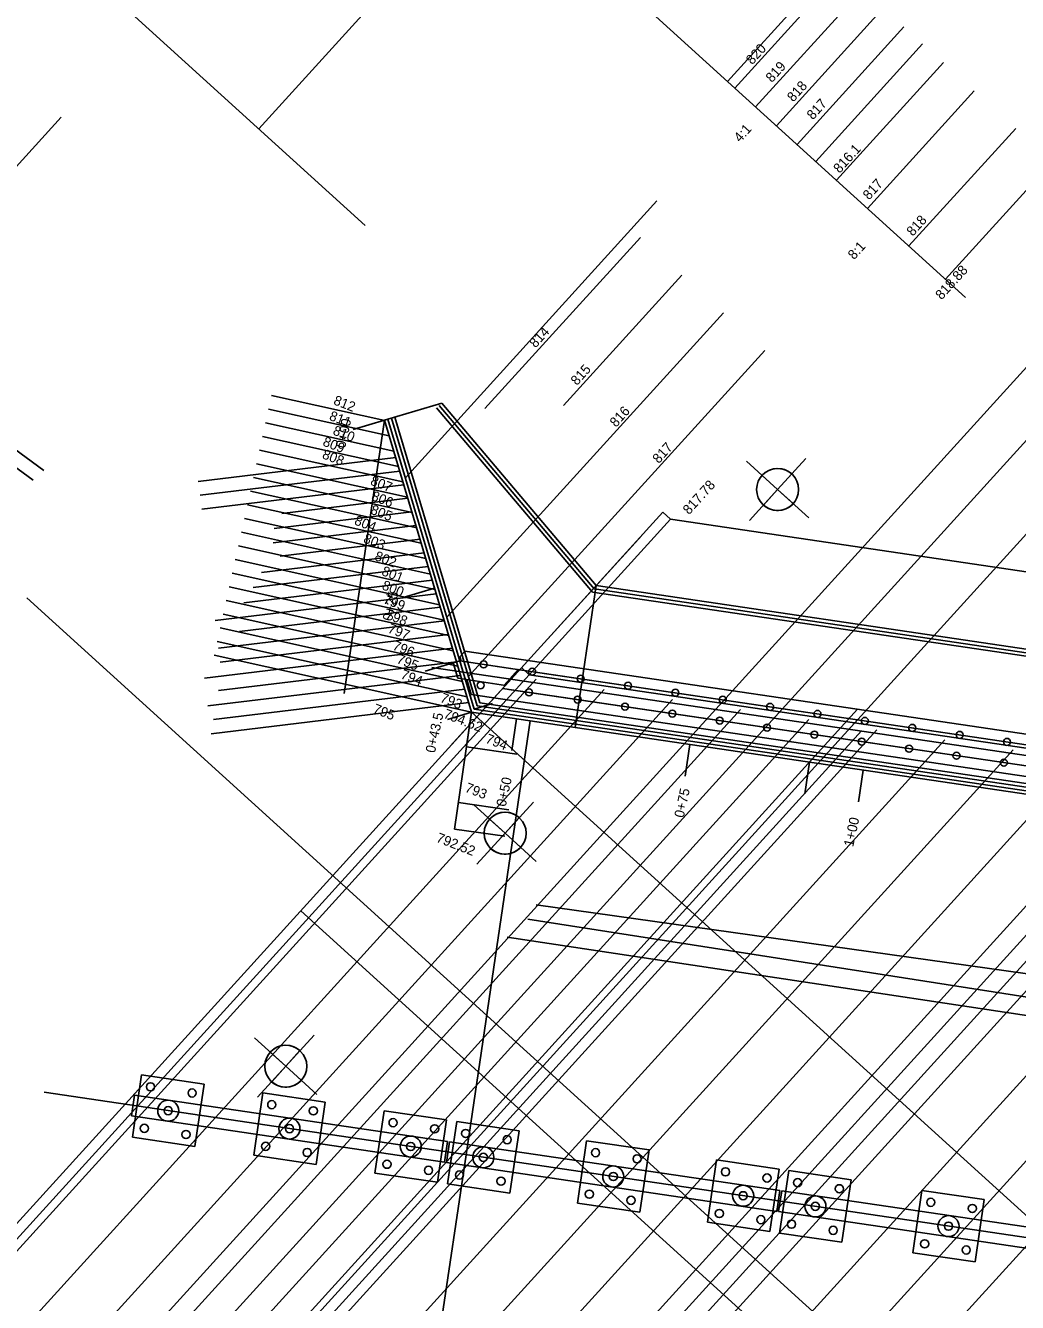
# Model space of a CAD drawing. Extents: x 1465887 to 1476191, y 569684 to 581027.
# Drawn here: x 1469836.1 to 1469977.6, y 574066.2 to 574248.6 of the extents above; entities that cross this region are included whole.
import ezdxf

# ---------------------------------------------------------------- set-up
doc = ezdxf.new("R2010")
doc.units = 0
for name, color, linetype in [('BR_P_Beam_Centerline', 7, 'Continuous'), ('BR_P_Brg_Centerline', 7, 'Continuous'), ('BR_P_Gen_Approach_Slab', 7, 'Continuous'), ('BR_P_Gen_Ground_Slope', 7, 'Continuous'), ('BR_P_Gen_Perforated_Pipe', 7, 'Continuous'), ('BR_P_Gen_Phase_Construction', 7, 'Continuous'), ('BR_P_Gen_Porous_Backfill', 7, 'Continuous'), ('BR_P_Gen_Profile_Grade', 7, 'Continuous'), ('BR_P_Gen_Slope_Protection', 7, 'Continuous'), ('BR_P_Rail_Object', 7, 'Continuous'), ('BR_P_Sub_Centerline', 7, 'Continuous'), ('BR_P_Sub_Deep_Centerline', 7, 'Continuous'), ('BR_P_Sub_Deep_Hidden', 7, 'Continuous'), ('BR_P_Sub_Foot_Hidden', 7, 'Continuous'), ('BR_P_Sub_Hidden', 7, 'Continuous'), ('BR_P_Sub_Object', 7, 'Continuous'), ('GT_Project_Soil_Boring', 7, 'Continuous'), ('PV_X_EOP', 7, 'Continuous'), ('PV_X_Shoulder', 7, 'Continuous'), ('SC_Scratch1', 7, 'Continuous'), ('SC_Scratch2', 7, 'Continuous'), ('UT_X_Water', 7, 'Continuous')]:
    doc.layers.add(name, color=color, linetype=linetype)

msp = doc.modelspace()

# ---------------------------------------------------------------- linework, layer by layer
at = {"layer": 'BR_P_Beam_Centerline'}
for p, q in [((1469797.88, 574032.91), (1469908.95, 574155.21)), ((1469807.6, 574031.47), (1469918.67, 574153.77)), ((1469817.33, 574030.03), (1469928.4, 574152.33)), ((1469827.05, 574028.59), (1469938.12, 574150.89)), ((1469836.78, 574027.15), (1469947.84, 574149.45)), ((1469846.5, 574025.71), (1469957.57, 574148.01)), ((1469856.23, 574024.27), (1469967.29, 574146.57)), ((1469865.95, 574022.83), (1469977.02, 574145.13)), ((1469875.67, 574021.39), (1469986.74, 574143.69)), ((1469885.4, 574019.95), (1469996.47, 574142.25)), ((1469895.12, 574018.51), (1470006.19, 574140.81)), ((1469904.85, 574017.07), (1470015.91, 574139.37)), ((1469914.57, 574015.63), (1470025.64, 574137.93)), ((1469924.3, 574014.19), (1470035.36, 574136.49))]:
    msp.add_line(p, q, dxfattribs=at)
at = {"layer": 'BR_P_Brg_Centerline'}
msp.add_line((1469894.04, 574156.91), (1470052.69, 574133.42), dxfattribs=at)
at = {"layer": 'BR_P_Gen_Approach_Slab'}
for p, q in [((1469928.13, 574178.07), (1470067.44, 574157.44)), ((1469907.96, 574155.86), (1470047.28, 574135.23))]:
    msp.add_line(p, q, dxfattribs=at)
at = {"layer": 'BR_P_Gen_Ground_Slope'}
for p, q in [((1469884.52, 574220.03), (1469752.3, 574340.1)), ((1469937.3, 574239.64), (1469952.56, 574256.43)), ((1469940.27, 574236.95), (1469955.52, 574253.75)), ((1469943.23, 574234.26), (1469958.48, 574251.06)), ((1469946.19, 574231.57), (1469961.44, 574248.37)), ((1469956.23, 574222.45), (1469971.48, 574239.25)), ((1469819.44, 574211.59), (1469841.12, 574235.46)), ((1469962.15, 574217.08), (1469977.4, 574233.87)), ((1469967.36, 574212.34), (1469982.61, 574229.14)), ((1469901.63, 574193.87), (1469923.82, 574218.31)), ((1469912.84, 574194.31), (1469929.75, 574212.93)), ((1469896.2, 574164.09), (1469935.67, 574207.55)), ((1469899.26, 574155.56), (1469941.59, 574202.17)), ((1469821.79, 574197.35), (1469838.65, 574185.03)), ((1469819.59, 574196.48), (1469837.16, 574183.64)), ((1469887.32, 574192.17), (1469871.18, 574195.74)), ((1469887.97, 574189.98), (1469870.75, 574193.79)), ((1469888.63, 574187.79), (1469870.32, 574191.84)), ((1469889.28, 574185.59), (1469869.88, 574189.89)), ((1469888.9, 574186.88), (1469860.72, 574183.47)), ((1469889.93, 574183.4), (1469869.45, 574187.93)), ((1469889.47, 574184.93), (1469860.96, 574181.48)), ((1469890.58, 574181.21), (1469869.02, 574185.98)), ((1469890.05, 574182.99), (1469861.2, 574179.5)), ((1469891.24, 574179.01), (1469868.59, 574184.03)), ((1469891.89, 574176.82), (1469868.16, 574182.08)), ((1469890.63, 574181.05), (1469872.65, 574178.87)), ((1469892.54, 574174.63), (1469867.72, 574180.12)), ((1469891.21, 574179.1), (1469871.56, 574176.72)), ((1469893.2, 574172.44), (1469867.29, 574178.17)), ((1469891.79, 574177.16), (1469871.38, 574174.69)), ((1469893.85, 574170.24), (1469866.86, 574176.22)), ((1469894.5, 574168.05), (1469866.43, 574174.26)), ((1469892.37, 574175.21), (1469872.38, 574172.79)), ((1469895.15, 574165.86), (1469865.99, 574172.31)), ((1469892.95, 574173.27), (1469869.73, 574170.46)), ((1469895.81, 574163.66), (1469865.56, 574170.36)), ((1469893.53, 574171.32), (1469868.57, 574168.3)), ((1469896.46, 574161.47), (1469865.13, 574168.41)), ((1469894.11, 574169.38), (1469867.22, 574166.13)), ((1469894.68, 574167.43), (1469863.12, 574163.62)), ((1469897.11, 574159.28), (1469864.7, 574166.45)), ((1469897.77, 574157.09), (1469864.26, 574164.5)), ((1469895.26, 574165.49), (1469866.61, 574162.02)), ((1469895.84, 574163.54), (1469863.6, 574159.64)), ((1469898.42, 574154.89), (1469863.83, 574162.55)), ((1469896.42, 574161.6), (1469863.84, 574157.66)), ((1469897, 574159.66), (1469861.59, 574155.37)), ((1469899.07, 574152.7), (1469863.4, 574160.6)), ((1469899.72, 574150.51), (1469862.97, 574158.64)), ((1469897.58, 574157.71), (1469863.6, 574153.6)), ((1469898.16, 574155.77), (1469862.07, 574151.4)), ((1469898.74, 574153.82), (1469862.88, 574149.48)), ((1469899.32, 574151.88), (1469862.55, 574147.43)), ((1469899.72, 574150.51), (1469897.3, 574133.83)), ((1469899, 574145.55), (1469906.18, 574144.51)), ((1469897.86, 574137.63), (1469905.03, 574136.59)), ((1469897.3, 574133.83), (1469904.48, 574132.79))]:
    msp.add_line(p, q, dxfattribs=at)
at = {"layer": 'BR_P_Gen_Perforated_Pipe'}
for p, q in [((1469894.7, 574193.98), (1469916.98, 574167.66)), ((1469895.08, 574194.3), (1469917.24, 574168.13)), ((1469888.27, 574192.48), (1469900.5, 574151.4)), ((1469888.75, 574192.63), (1469900.89, 574151.85)), ((1469917.24, 574168.13), (1470044.7, 574149.26)), ((1469916.98, 574167.66), (1470044.86, 574148.73)), ((1469900.89, 574151.85), (1470043.82, 574130.69)), ((1469899.72, 574150.51), (1469997.64, 574061.59)), ((1469900.5, 574151.4), (1470044.02, 574130.16))]:
    msp.add_line(p, q, dxfattribs=at)
at = {"layer": 'BR_P_Gen_Phase_Construction'}
for p, q in [((1469839.72, 574024.19), (1469954.83, 574150.94)), ((1469845.12, 574026.42), (1469955.38, 574147.83)), ((1469886.75, 574017.22), (1470001.86, 574143.98)), ((1469892.16, 574019.46), (1469999.98, 574138.19))]:
    msp.add_line(p, q, dxfattribs=at)
at = {"layer": 'BR_P_Gen_Porous_Backfill'}
for p, q in [((1469887.79, 574192.34), (1469895.46, 574194.62)), ((1469895.46, 574194.62), (1469917.5, 574168.6)), ((1469917.5, 574168.6), (1470044.55, 574149.79))]:
    msp.add_line(p, q, dxfattribs=at)
at = {"layer": 'BR_P_Gen_Profile_Grade'}
msp.add_line((1465892.5, 569689.56), (1476184.47, 581022.69), dxfattribs=at)
at = {"layer": 'BR_P_Gen_Slope_Protection'}
for p, q in [((1469887.31, 574192.2), (1469887.79, 574192.34)), ((1469887.31, 574192.2), (1469899.72, 574150.51)), ((1469887.79, 574192.34), (1469900.11, 574150.95)), ((1469899.72, 574150.51), (1470043.8, 574129.18)), ((1469900.11, 574150.95), (1470044.4, 574129.59))]:
    msp.add_line(p, q, dxfattribs=at)
at = {"layer": 'BR_P_Rail_Object'}
for p, q in [((1469774.81, 574011.47), (1469927.02, 574179.08)), ((1469928.13, 574178.07), (1469927.02, 574179.08)), ((1469775.92, 574010.46), (1469928.13, 574178.07)), ((1469907.96, 574155.86), (1469906.85, 574156.87))]:
    msp.add_line(p, q, dxfattribs=at)
at = {"layer": 'BR_P_Sub_Centerline'}
msp.add_line((1469838.73, 574096.23), (1469997.31, 574072.75), dxfattribs=at)
at = {"layer": 'BR_P_Sub_Deep_Centerline'}
for p, q in [((1469903.37, 574157.04), (1470048.77, 574135.52)), ((1470044.7, 574133.09), (1469905.02, 574153.77))]:
    msp.add_line(p, q, dxfattribs=at)
at = {"layer": 'BR_P_Sub_Deep_Hidden'}
for centre, radius in [((1469901.45, 574157.33), 0.5), ((1469908.37, 574156.3), 0.5), ((1469915.3, 574155.28), 0.5), ((1469901.01, 574154.36), 0.5), ((1469907.93, 574153.34), 0.5), ((1469922.06, 574154.28), 0.5), ((1469928.82, 574153.28), 0.5), ((1469914.86, 574152.31), 0.5), ((1469921.62, 574151.31), 0.5), ((1469935.58, 574152.28), 0.5), ((1469942.34, 574151.27), 0.5), ((1469928.38, 574150.31), 0.5), ((1469935.14, 574149.31), 0.5), ((1469949.1, 574150.27), 0.5), ((1469955.86, 574149.27), 0.5), ((1469941.9, 574148.31), 0.5), ((1469962.62, 574148.27), 0.5), ((1469948.66, 574147.31), 0.5), ((1469955.42, 574146.31), 0.5), ((1469969.38, 574147.27), 0.5), ((1469976.14, 574146.27), 0.5), ((1469962.18, 574145.3), 0.5), ((1469968.94, 574144.3), 0.5), ((1469975.7, 574143.3), 0.5), ((1469853.89, 574097.02), 0.583), ((1469859.83, 574096.14), 0.583), ((1469856.42, 574093.61), 0.583), ((1469871.2, 574094.46), 0.583), ((1469877.14, 574093.58), 0.583), ((1469853.01, 574091.08), 0.583), ((1469873.73, 574091.05), 0.583), ((1469888.52, 574091.89), 0.583), ((1469894.45, 574091.01), 0.583), ((1469858.95, 574090.21), 0.583), ((1469898.87, 574090.36), 0.583), ((1469904.81, 574089.48), 0.583), ((1469870.33, 574088.52), 0.583), ((1469876.26, 574087.64), 0.583), ((1469891.04, 574088.49), 0.583), ((1469917.42, 574087.61), 0.583), ((1469887.64, 574085.96), 0.583), ((1469901.4, 574086.95), 0.583), ((1469923.35, 574086.74), 0.583), ((1469893.57, 574085.08), 0.583), ((1469897.99, 574084.43), 0.583), ((1469903.93, 574083.55), 0.583), ((1469919.95, 574084.21), 0.583), ((1469935.97, 574084.87), 0.583), ((1469941.9, 574083.99), 0.583), ((1469946.27, 574083.34), 0.583), ((1469952.21, 574082.46), 0.583), ((1469916.54, 574081.68), 0.583), ((1469922.48, 574080.8), 0.583), ((1469938.49, 574081.46), 0.583), ((1469948.8, 574079.94), 0.583), ((1469965.27, 574080.53), 0.583), ((1469935.09, 574078.93), 0.583), ((1469941.02, 574078.05), 0.583), ((1469971.21, 574079.65), 0.583), ((1469945.39, 574077.41), 0.583), ((1469951.33, 574076.53), 0.583), ((1469967.8, 574077.12), 0.583), ((1469964.39, 574074.59), 0.583), ((1469970.33, 574073.72), 0.583)]:
    msp.add_circle(centre, radius, dxfattribs=at)
at = {"layer": 'BR_P_Sub_Foot_Hidden'}
for p, q in [((1469898.06, 574158.43), (1469898.76, 574159.24)), ((1469898.76, 574159.24), (1470049.69, 574136.9)), ((1469898.06, 574158.43), (1469898.25, 574157.8)), ((1469899.03, 574155.16), (1469899.66, 574153.04)), ((1469899.66, 574153.04), (1470045.83, 574131.4)), ((1469851.31, 574089.82), (1469852.63, 574098.72)), ((1469852.63, 574098.72), (1469861.53, 574097.4)), ((1469861.53, 574097.4), (1469860.21, 574088.5)), ((1469868.62, 574087.26), (1469869.94, 574096.16)), ((1469869.94, 574096.16), (1469878.84, 574094.84)), ((1469878.84, 574094.84), (1469877.52, 574085.94)), ((1469885.93, 574084.69), (1469887.25, 574093.6)), ((1469887.25, 574093.6), (1469896.15, 574092.28)), ((1469896.15, 574092.28), (1469894.84, 574083.38)), ((1469896.29, 574083.16), (1469897.61, 574092.06)), ((1469897.61, 574092.06), (1469906.51, 574090.75)), ((1469851.31, 574089.82), (1469860.21, 574088.5)), ((1469906.51, 574090.75), (1469905.19, 574081.84)), ((1469914.84, 574080.42), (1469916.15, 574089.32)), ((1469916.15, 574089.32), (1469925.06, 574088)), ((1469925.06, 574088), (1469923.74, 574079.1)), ((1469868.62, 574087.26), (1469877.52, 574085.94)), ((1469933.38, 574077.67), (1469934.7, 574086.57)), ((1469934.7, 574086.57), (1469943.61, 574085.25)), ((1469885.93, 574084.69), (1469894.84, 574083.38)), ((1469943.61, 574085.25), (1469942.29, 574076.35)), ((1469943.69, 574076.14), (1469945.01, 574085.05)), ((1469945.01, 574085.05), (1469953.91, 574083.73)), ((1469896.29, 574083.16), (1469905.19, 574081.84)), ((1469953.91, 574083.73), (1469952.59, 574074.83)), ((1469962.69, 574073.33), (1469964.01, 574082.23)), ((1469964.01, 574082.23), (1469972.91, 574080.92)), ((1469972.91, 574080.92), (1469971.59, 574072.01)), ((1469914.84, 574080.42), (1469923.74, 574079.1)), ((1469933.38, 574077.67), (1469942.29, 574076.35)), ((1469943.69, 574076.14), (1469952.59, 574074.83)), ((1469962.69, 574073.33), (1469971.59, 574072.01))]:
    msp.add_line(p, q, dxfattribs=at)
at = {"layer": 'BR_P_Sub_Hidden'}
for p, q in [((1469904.15, 574153.9), (1469906.58, 574156.57)), ((1469904.36, 574154.37), (1469906.38, 574156.6)), ((1469906.58, 574156.57), (1470049.47, 574135.41)), ((1469904.15, 574153.9), (1470047.04, 574132.74)), ((1469851.61, 574095.84), (1469851.17, 574092.87)), ((1469851.61, 574095.84), (1469896.29, 574089.23)), ((1469895.85, 574086.26), (1469851.17, 574092.87)), ((1469895.85, 574086.26), (1469896.29, 574089.23)), ((1469896.59, 574089.18), (1469896.15, 574086.21)), ((1469896.59, 574089.18), (1469943.74, 574082.2)), ((1469943.3, 574079.23), (1469896.15, 574086.21)), ((1469943.3, 574079.23), (1469943.74, 574082.2)), ((1469943.99, 574082.16), (1469943.55, 574079.2)), ((1469943.99, 574082.16), (1469992.05, 574075.05)), ((1469991.61, 574072.08), (1469943.55, 574079.2))]:
    msp.add_line(p, q, dxfattribs=at)
msp.add_lwpolyline([(1469904.36, 574154.37), (1469904.56, 574154.34), (1469906.58, 574156.57), (1469906.38, 574156.6)], close=True, dxfattribs=at)
for centre in [(1469856.42, 574093.61), (1469873.73, 574091.05), (1469891.04, 574088.49), (1469901.4, 574086.95), (1469919.95, 574084.21), (1469938.49, 574081.46), (1469948.8, 574079.94), (1469967.8, 574077.12)]:
    msp.add_circle(centre, 1.5, dxfattribs=at)
at = {"layer": 'BR_P_Sub_Object'}
for p, q in [((1469898.07, 574157.83), (1469897.11, 574157.54)), ((1469897.11, 574157.54), (1469897.76, 574155.35)), ((1469898.07, 574157.83), (1469906.58, 574156.57)), ((1469897.76, 574155.35), (1469904.56, 574154.34))]:
    msp.add_line(p, q, dxfattribs=at)
at = {"layer": 'GT_Project_Soil_Boring'}
for p, q in [((1469943.41, 574182.31), (1469938.97, 574186.34)), ((1469943.41, 574182.31), (1469947.45, 574186.75)), ((1469945.43, 574184.53), (1469943.41, 574182.31)), ((1469943.41, 574182.31), (1469941.19, 574184.33)), ((1469943.41, 574182.31), (1469939.38, 574177.87)), ((1469941.4, 574180.09), (1469943.41, 574182.31)), ((1469943.41, 574182.31), (1469947.85, 574178.28)), ((1469943.41, 574182.31), (1469945.63, 574180.29)), ((1469904.51, 574133.23), (1469900.06, 574137.27)), ((1469904.51, 574133.23), (1469908.54, 574137.68)), ((1469904.51, 574133.23), (1469902.29, 574135.25)), ((1469906.52, 574135.45), (1469904.51, 574133.23)), ((1469904.51, 574133.23), (1469900.47, 574128.79)), ((1469902.49, 574131.01), (1469904.51, 574133.23)), ((1469904.51, 574133.23), (1469908.95, 574129.2)), ((1469904.51, 574133.23), (1469906.73, 574131.22)), ((1469873.2, 574099.96), (1469877.24, 574104.4)), ((1469873.2, 574099.96), (1469868.76, 574104)), ((1469873.2, 574099.96), (1469870.98, 574101.98)), ((1469875.22, 574102.18), (1469873.2, 574099.96)), ((1469873.2, 574099.96), (1469869.17, 574095.52)), ((1469871.19, 574097.74), (1469873.2, 574099.96)), ((1469873.2, 574099.96), (1469877.64, 574095.93)), ((1469873.2, 574099.96), (1469875.42, 574097.95))]:
    msp.add_line(p, q, dxfattribs=at)
for centre in [(1469943.41, 574182.31), (1469904.51, 574133.23), (1469873.2, 574099.96)]:
    msp.add_circle(centre, 3, dxfattribs=at)
for centre, start, end in [((1469943.41, 574182.31), 47.7565, 137.7565), ((1469943.41, 574182.31), 227.7565, 317.7565), ((1469904.51, 574133.23), 47.7565, 137.7565), ((1469904.51, 574133.23), 227.7565, 317.7565), ((1469873.2, 574099.96), 47.7565, 137.7565), ((1469873.2, 574099.96), 227.7565, 317.7565)]:
    msp.add_arc(centre, 3, start, end, dxfattribs=at)
at = {"layer": 'PV_X_EOP'}
msp.add_line((1469904.79, 574118.39), (1470006.8, 574102.99), dxfattribs=at)
at = {"layer": 'PV_X_Shoulder'}
msp.add_line((1469908.94, 574123), (1470011.71, 574108.53), dxfattribs=at)
at = {"layer": 'SC_Scratch1'}
for p, q in [((1465887.32, 569694.27), (1476179.29, 581027.4)), ((1465899.17, 569683.51), (1476191.13, 581016.64)), ((1469869.34, 574233.82), (1472383.88, 577002.73)), ((1469936.27, 574240.58), (1469951.52, 574257.38)), ((1469918.13, 574257.05), (1469970.23, 574209.74)), ((1469948.85, 574229.15), (1469964.11, 574245.95)), ((1469951.81, 574226.46), (1469967.07, 574243.26)), ((1469890.28, 574183.99), (1469926.18, 574223.52)), ((1469881.54, 574153.2), (1469887.31, 574192.2)), ((1469882.83, 574190.86), (1469887.31, 574192.2)), ((1469896.66, 574145.65), (1469924.01, 574175.76)), ((1469889.96, 574166.9), (1469894.45, 574168.24)), ((1469917.5, 574168.6), (1469914.5, 574148.32)), ((1469893.11, 574156.35), (1469897.59, 574157.69)), ((1469900.11, 574150.95), (1469902.7, 574151.73)), ((1469896.28, 574149.48), (1469899.72, 574150.51)), ((1469899.05, 574145.98), (1469899.72, 574150.51)), ((1469898.93, 574087.32), (1469908.1, 574149.27)), ((1469905.48, 574145.03), (1469906.15, 574149.56)), ((1469930.21, 574141.36), (1469930.88, 574145.89)), ((1469947.28, 574138.84), (1469947.95, 574143.37)), ((1469954.94, 574137.7), (1469955.61, 574142.23)), ((1469889.68, 574024.88), (1469898.93, 574087.32))]:
    msp.add_line(p, q, dxfattribs=at)
at = {"layer": 'SC_Scratch2'}
for p, q in [((1469967.62, 574047.52), (1469836.22, 574166.85)), ((1469964.17, 574041.49), (1469875.33, 574122.16))]:
    msp.add_line(p, q, dxfattribs=at)
at = {"layer": 'UT_X_Water'}
msp.add_line((1469907.74, 574120.94), (1470009.3, 574105.12), dxfattribs=at)

# ---------------------------------------------------------------- texts
at = {"layer": 'BR_P_Gen_Ground_Slope'}
for s, rotation, p in [('820', 47.7564, (1469939.78, 574242.88)), ('819', 47.7564, (1469942.59, 574240.33)), ('818', 47.7564, (1469945.64, 574237.56)), ('817', 47.7564, (1469948.45, 574235.01)), ('4:1', 47.7564, (1469938.05, 574231.79)), ('816.1', 47.7564, (1469952.25, 574227.38)), ('817', 47.7564, (1469956.45, 574223.57)), ('818', 47.7564, (1469962.7, 574218.39)), ('8:1', 47.7564, (1469954.32, 574215.03)), ('818.88', 47.7564, (1469966.81, 574209.31)), ('814', 47.7564, (1469908.85, 574202.44)), ('815', 47.7564, (1469914.76, 574197.08)), ('812', 338.5632, (1469879.9, 574194.51)), ('816', 47.7564, (1469920.33, 574191.11)), ('811', 338.5632, (1469879.29, 574192.29)), ('810', 338.5632, (1469879.81, 574190.2)), ('809', 338.5632, (1469878.37, 574188.62)), ('817', 47.7564, (1469926.44, 574185.93)), ('808', 338.5632, (1469878.29, 574186.81)), ('807', 338.5632, (1469885.16, 574183.04)), ('817.78', 47.7564, (1469930.76, 574178.63)), ('806', 338.5632, (1469885.3, 574180.85)), ('805', 338.5632, (1469885.18, 574178.9)), ('804', 338.5632, (1469882.88, 574177.36)), ('803', 338.5632, (1469884.17, 574174.79)), ('802', 338.5632, (1469885.76, 574172.28)), ('801', 338.5632, (1469886.77, 574170.13)), ('800', 338.5632, (1469886.82, 574168.1)), ('799', 338.5632, (1469887, 574166.12)), ('798', 338.5632, (1469887.33, 574163.94)), ('797', 338.5632, (1469887.66, 574161.93)), ('796', 338.5632, (1469888.34, 574159.49)), ('795', 338.5632, (1469888.91, 574157.57)), ('794', 338.5632, (1469889.49, 574155.38)), ('795', 338.5632, (1469885.54, 574150.46)), ('793', 338.5632, (1469895.13, 574152.03)), ('794.62', 338.5632, (1469895.61, 574149.74)), ('794', 338.5632, (1469901.6, 574146.18)), ('793', 338.5632, (1469898.68, 574139.2)), ('792.52', 338.5632, (1469894.57, 574132.05))]:
    msp.add_text(s, height=1.4, rotation=rotation, dxfattribs=at).set_placement(p)
at = {"layer": 'SC_Scratch1'}
for s, p in [('0+00', (1469881.67, 574188.14)), ('0+25', (1469888.37, 574163.44)), ('0+43.5', (1469894.49, 574144.62)), ('0+50', (1469904.59, 574136.94)), ('0+75', (1469930, 574135.36)), ('1+00', (1469954.19, 574131.21))]:
    msp.add_text(s, height=1.4, rotation=77.7564, dxfattribs=at).set_placement(p)

doc.saveas('drawing.dxf')
